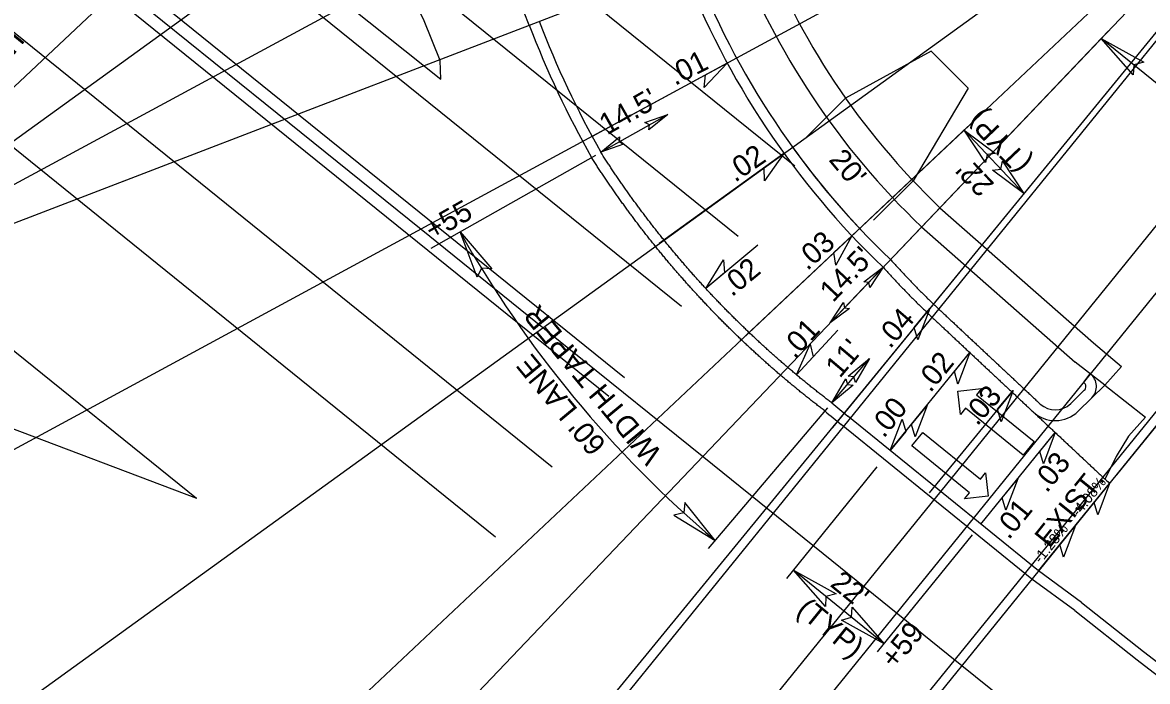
# Model space of a CAD drawing. Extents: x 1486489 to 1490134, y 497089 to 500876.
# Drawn here: x 1488844.3 to 1489056.4, y 499014.9 to 499139.1 of the extents above; entities that cross this region are included whole.
import ezdxf

# ---------------------------------------------------------------- set-up
doc = ezdxf.new("R2010")
doc.units = 0
for name, color, linetype in [('DEV PRELIMINARY STAMP CELL', 7, 'Continuous'), ('Gray Area Fill Shapes', 7, 'Continuous'), ('Old_Level_9', 7, 'Continuous'), ('Prop Conc Drive Radius Type', 7, 'Continuous'), ('Prop Conc Driveway', 7, 'Continuous'), ('Prop Horizontal Alignment Station Label', 7, 'Continuous'), ('Prop Rem of Exist Asph Pvmt', 7, 'Continuous'), ('Prop Text', 7, 'Continuous'), ('Scratch_Level_0', 7, 'Continuous'), ('Scratch_Level_5', 7, 'Continuous'), ('Sheet Border Standard 30in CELL', 7, 'Continuous'), ('Sheet Clip Boundary CELL', 7, 'Continuous'), ('Sheet Cutting Line CELL', 7, 'Continuous'), ('Sheet Data Field CELL', 7, 'Continuous'), ('Sheet Plan CELL', 7, 'Continuous'), ('Sheet Plot Border Inside CELL', 7, 'Continuous'), ('Sheet Plot Border Outside CELL', 7, 'Continuous'), ('Sheet Sticker Exception Certification CELL', 7, 'Continuous'), ('Sheet Title CELL', 7, 'Continuous')]:
    doc.layers.add(name, color=color, linetype=linetype)

msp = doc.modelspace()

# ---------------------------------------------------------------- linework, layer by layer
at = {"layer": 'DEV PRELIMINARY STAMP CELL'}
for p, q in [((1488982.96, 499097.13), (1488973.14, 499089)), ((1488998.04, 499081.13), (1488990.22, 499072.74)), ((1489007.94, 499058.43), (1489022.93, 499076.91)), ((1489025.03, 499044.57), (1489039.04, 499061.85)), ((1488988.42, 499034.35), (1489005.44, 499055.35)), ((1489005.51, 499020.49), (1489023.42, 499042.58)), ((1489006.77, 499022.04), (1488989.68, 499035.9))]:
    msp.add_line(p, q, dxfattribs=at)
for points in [[(1488973.14, 499089), (1488976.48, 499094.37), (1488976.7, 499091.95)], [(1488990.22, 499072.74), (1488992.85, 499078.5), (1488993.38, 499076.13)], [(1489022.93, 499076.91), (1489020.7, 499070.99), (1489020.02, 499073.32)], [(1489014.87, 499066.97), (1489012.64, 499061.05), (1489011.96, 499063.38)], [(1489007.94, 499058.43), (1489010.17, 499064.35), (1489010.85, 499062.02)], [(1489039.04, 499061.85), (1489036.81, 499055.93), (1489036.12, 499058.25)], [(1489031.96, 499053.12), (1489029.73, 499047.19), (1489029.04, 499049.52)], [(1489049.29, 499052.26), (1489047.06, 499046.34), (1489046.37, 499048.67)], [(1489042.83, 499044.3), (1489040.61, 499038.38), (1489039.92, 499040.71)], [(1488995.69, 499029.03), (1488989.68, 499035.9), (1488997.71, 499031.44), (1488995.81, 499030.92)], [(1489000.75, 499028.92), (1489006.77, 499022.04), (1488998.73, 499026.5), (1489000.63, 499027.02)]]:
    msp.add_lwpolyline(points, close=True, dxfattribs=at)
at = {"layer": 'Old_Level_9'}
msp.add_lwpolyline([(1489125.56, 498933.79), (1489105.79, 498950), (1489083.46, 498967.96), (1489053.28, 498992.22), (1489018.86, 499019.95), (1488995.28, 499038.96), (1488972.75, 499057.15), (1488947.35, 499077.62), (1488919.48, 499100.08), (1488890.07, 499123.82), (1488841.68, 499162.79)], dxfattribs=at)
at = {"layer": 'Prop Conc Drive Radius Type'}
msp.add_arc((1489113.94, 499205.5), 153.5, 215.8585, 223.5075, dxfattribs=at)
at = {"layer": 'Prop Conc Driveway'}
for p, q in [((1489015.64, 499133.75), (1488999.51, 499124.84)), ((1489022.63, 499126.72), (1489015.64, 499133.75)), ((1489022.63, 499126.72), (1489012.24, 499109.29)), ((1488999.51, 499124.84), (1488991.97, 499117.34)), ((1489012.24, 499109.29), (1489004.79, 499101.89))]:
    msp.add_line(p, q, dxfattribs=at)
at = {"layer": 'Prop Horizontal Alignment Station Label'}
for p, q in [((1489017.3, 499104.21), (1489046.26, 499078.72)), ((1489013.84, 499100.59), (1489042.81, 499075.1)), ((1489046.26, 499078.72), (1489051.56, 499074.32)), ((1489048.37, 499070.79), (1489042.81, 499075.1)), ((1489048.37, 499070.79), (1489051.56, 499074.32))]:
    msp.add_line(p, q, dxfattribs=at)
for radius in [140, 145]:
    msp.add_arc((1489113.94, 499205.5), radius, 201.0099, 226.343, dxfattribs=at)
at = {"layer": 'Prop Rem of Exist Asph Pvmt'}
for points in [[(1488923.18, 499128.44), (1488923.08, 499131.98), (1488920.07, 499139.43), (1488916.58, 499146.6), (1488912.5, 499153.45), (1488908.04, 499160.04), (1488903.34, 499166.45), (1488901.34, 499168.89)], [(1488852.51, 499162.38), (1488857.14, 499162.31), (1488868.78, 499160.49), (1488887.58, 499153.02), (1488906.23, 499141.98), (1488923.18, 499128.44)]]:
    msp.add_lwpolyline(points, dxfattribs=at)
at = {"layer": 'Prop Text'}
for p, q in [((1488774.7, 499063.04), (1489066.03, 499337.13)), ((1488858.52, 498937.81), (1489134.65, 499227.2)), ((1489133.24, 499228.47), (1488881.33, 498917.76)), ((1489156.48, 499209.63), (1488904.57, 498898.92)), ((1489167.42, 499200.76), (1488915.51, 498890.05)), ((1488916.88, 498888.94), (1489168.79, 499199.65))]:
    msp.add_line(p, q, dxfattribs=at)
msp.add_lwpolyline([(1488898.42, 498903.91), (1488898.42, 498903.91), (1489150.33, 499214.62)], dxfattribs=at)
at = {"layer": 'Scratch_Level_0'}
for p in [(1488772.04, 499134.22), (1488750.83, 499097.17)]:
    msp.add_line(p, (1488877.12, 499049.47), dxfattribs=at)
at = {"layer": 'Scratch_Level_5'}
for p, q in [((1489044.43, 499071.32), (1489045.65, 499072.9)), ((1489044.52, 499069.81), (1489041.95, 499067.29)), ((1489034.65, 499034.2), (1488998.7, 499063.35)), ((1489042.71, 499028.27), (1489034.65, 499034.2))]:
    msp.add_line(p, q, dxfattribs=at)
msp.add_lwpolyline([(1489042.71, 499028.27), (1489054.46, 499018.99), (1489094.18, 498988.49), (1489125.68, 498966.85), (1489130.23, 498964.14)], dxfattribs=at)
for centre, radius, start, end in [((1488796.55, 499083.6), 153.5, 21.0099, 51.1156), ((1489113.94, 499205.5), 153.5, 201.0099, 226.343), ((1489113.94, 499205.5), 186.5, 201.0099, 209.4913), ((1489043.82, 499070.53), 1, 314.53, 52.2567), ((1489039.05, 499070.24), 4.14, 226.9121, 314.53), ((1489113.94, 499205.5), 183, 229.7133, 230.9669)]:
    msp.add_arc(centre, radius, start, end, dxfattribs=at)
for points in [[(1488995.61, 499065.9), (1488994.92, 499066.43), (1488994.23, 499066.97), (1488993.53, 499067.5), (1488992.85, 499068.04), (1488992.16, 499068.59), (1488991.48, 499069.13), (1488990.8, 499069.68), (1488990.12, 499070.24), (1488989.44, 499070.8), (1488988.77, 499071.36), (1488988.1, 499071.92), (1488987.43, 499072.49), (1488986.76, 499073.06), (1488986.1, 499073.63), (1488985.44, 499074.21), (1488984.78, 499074.79), (1488984.13, 499075.37), (1488983.48, 499075.96), (1488982.83, 499076.55), (1488982.18, 499077.15), (1488981.53, 499077.74), (1488980.89, 499078.34), (1488980.25, 499078.95), (1488979.62, 499079.55), (1488978.98, 499080.16), (1488978.35, 499080.78), (1488977.72, 499081.39), (1488977.1, 499082.01), (1488976.47, 499082.64), (1488975.85, 499083.26), (1488975.24, 499083.89), (1488974.62, 499084.52), (1488974.01, 499085.16), (1488973.4, 499085.79), (1488972.8, 499086.44), (1488972.2, 499087.08), (1488971.6, 499087.73), (1488971, 499088.38), (1488970.41, 499089.03), (1488969.81, 499089.69), (1488969.23, 499090.35), (1488968.64, 499091.01), (1488968.06, 499091.67), (1488967.48, 499092.34), (1488966.91, 499093.01), (1488966.33, 499093.69), (1488965.76, 499094.36), (1488965.2, 499095.04), (1488964.63, 499095.73), (1488964.07, 499096.41), (1488963.52, 499097.1), (1488962.96, 499097.79), (1488962.41, 499098.49), (1488961.87, 499099.18), (1488961.32, 499099.88), (1488960.78, 499100.58), (1488960.24, 499101.29), (1488959.71, 499102), (1488959.18, 499102.71), (1488958.65, 499103.42), (1488958.12, 499104.14), (1488957.6, 499104.86), (1488957.08, 499105.58), (1488956.57, 499106.3), (1488956.06, 499107.03), (1488955.55, 499107.76), (1488955.05, 499108.49), (1488954.54, 499109.22), (1488954.05, 499109.96), (1488953.55, 499110.7), (1488953.06, 499111.44), (1488952.57, 499112.19), (1488951.61, 499113.69)], [(1489007.98, 499094.44), (1489008.47, 499093.9), (1489008.96, 499093.35), (1489009.46, 499092.81), (1489009.96, 499092.27), (1489010.46, 499091.73), (1489010.97, 499091.2), (1489011.47, 499090.67), (1489011.99, 499090.14), (1489012.5, 499089.61), (1489013.01, 499089.08), (1489013.53, 499088.56), (1489014.06, 499088.04), (1489014.58, 499087.52), (1489015.11, 499087), (1489015.64, 499086.49), (1489016.17, 499085.98), (1489016.71, 499085.46), (1489017.3, 499084.91), (1489017.9, 499084.35), (1489018.49, 499083.8), (1489019.08, 499083.24), (1489019.68, 499082.69), (1489020.27, 499082.13), (1489020.86, 499081.57), (1489021.46, 499081.02), (1489022.05, 499080.46), (1489022.64, 499079.91), (1489023.24, 499079.35), (1489023.83, 499078.8), (1489024.43, 499078.24), (1489025.02, 499077.69), (1489025.61, 499077.13), (1489026.21, 499076.58), (1489026.8, 499076.02), (1489027.39, 499075.47), (1489027.99, 499074.91), (1489028.58, 499074.36), (1489029.17, 499073.8), (1489029.77, 499073.25), (1489030.36, 499072.69), (1489030.96, 499072.14), (1489031.55, 499071.58), (1489032.14, 499071.02), (1489032.74, 499070.47), (1489033.33, 499069.91), (1489033.92, 499069.36), (1489034.52, 499068.8), (1489035.11, 499068.25), (1489035.7, 499067.69), (1489036.22, 499067.21)]]:
    msp.add_spline(points, degree=3, dxfattribs=at)
at = {"layer": 'Sheet Border Standard 30in CELL'}
for p, q in [((1489066.03, 499337.13), (1488774.7, 499063.04)), ((1488772.23, 499066.03), (1489096.5, 499300.23)), ((1489121.95, 499259.71), (1488770.16, 499069.32)), ((1488879.44, 498919.3), (1489132.96, 499228.7)), ((1489135.79, 499226.06), (1488844.47, 498951.95)), ((1488814, 498988.85), (1489138.26, 499223.06)), ((1489140.33, 499219.78), (1488788.55, 499029.37)), ((1488768.54, 499072.84), (1489141.95, 499216.25))]:
    msp.add_line(p, q, dxfattribs=at)
at = {"layer": 'Sheet Clip Boundary CELL'}
msp.add_arc((1489043.82, 499070.53), 3, 314.53, 52.2567, dxfattribs=at)
at = {"layer": 'Sheet Cutting Line CELL'}
for p, q in [((1489049.1, 499137.54), (1489008.6, 499095.1)), ((1489089.68, 499102.08), (1489047.72, 499136.1)), ((1488953.35, 499114.67), (1488965.97, 499121.81)), ((1488921.37, 499096.59), (1488952.41, 499114.14)), ((1489090.94, 499103.63), (1489050.58, 499053.85)), ((1488996.59, 499082.5), (1489006.6, 499093)), ((1488996.91, 499067.43), (1489004.02, 499075.82)), ((1488973.63, 499039.97), (1488996.14, 499066.52))]:
    msp.add_line(p, q, dxfattribs=at)
msp.add_arc((1489113.94, 499205.5), 215, 209.4913, 229.7133, dxfattribs=at)
at = {"layer": 'Sheet Data Field CELL'}
for p, q in [((1488977.19, 499131.48), (1488951.69, 499117.67)), ((1489022.54, 499119.5), (1489000.69, 499098.94)), ((1489033.14, 499106.87), (1489021.86, 499118.86)), ((1488987.89, 499114.45), (1488964.38, 499097.47)), ((1489034.4, 499108.42), (1489015.39, 499085.22)), ((1489000.69, 499098.94), (1488979.57, 499079.07)), ((1489015.39, 499085.22), (1488997.01, 499062.78)), ((1489031.11, 499069.79), (1489015.27, 499050.46))]:
    msp.add_line(p, q, dxfattribs=at)
for points in [[(1488977.19, 499131.48), (1488972.87, 499126.86), (1488973.12, 499129.27)], [(1489025.89, 499112.76), (1489021.86, 499118.86), (1489027.75, 499114.46), (1489026.19, 499114.25)], [(1488987.89, 499114.45), (1488984.2, 499109.31), (1488984.14, 499111.74)], [(1489029.11, 499112.97), (1489033.14, 499106.87), (1489027.24, 499111.27), (1489028.81, 499111.48)], [(1489000.69, 499098.94), (1488997.69, 499093.37), (1488997.32, 499095.77)], [(1489015.39, 499085.22), (1489013.13, 499079.31), (1489012.46, 499081.64)], [(1489031.11, 499069.79), (1489028.85, 499063.89), (1489028.17, 499066.22)]]:
    msp.add_lwpolyline(points, close=True, dxfattribs=at)
at = {"layer": 'Sheet Plan CELL'}
for p, q in [((1488989.91, 499112.07), (1488678.54, 499363.17)), ((1488667.87, 499349.94), (1488979.24, 499098.84)), ((1488968.56, 499085.6), (1488657.2, 499336.7)), ((1488646.42, 499323.34), (1488957.79, 499072.24)), ((1488954.87, 499068.62), (1488643.5, 499319.72)), ((1488632.83, 499306.48), (1488944.2, 499055.38)), ((1488933.52, 499042.15), (1488622.16, 499293.25))]:
    msp.add_line(p, q, dxfattribs=at)
at = {"layer": 'Sheet Plot Border Inside CELL'}
for p, q in [((1489020.7, 499069.64), (1489025.16, 499070.15)), ((1489021.19, 499065.25), (1489020.7, 499069.64)), ((1489025.16, 499070.15), (1489024.22, 499068.98)), ((1489024.22, 499068.98), (1489035.09, 499060.16)), ((1489022.14, 499066.42), (1489021.19, 499065.25)), ((1489033.01, 499057.6), (1489022.14, 499066.42)), ((1489012.01, 499059.31), (1489014.09, 499061.87)), ((1489014.09, 499061.87), (1489024.97, 499053.06)), ((1489035.09, 499060.16), (1489033.01, 499057.6)), ((1489022.89, 499050.49), (1489012.01, 499059.31)), ((1489024.97, 499053.06), (1489025.91, 499054.22)), ((1489025.91, 499054.22), (1489026.41, 499049.83)), ((1489021.94, 499049.33), (1489022.89, 499050.49)), ((1489026.41, 499049.83), (1489021.94, 499049.33))]:
    msp.add_line(p, q, dxfattribs=at)
at = {"layer": 'Sheet Plot Border Outside CELL'}
for points in [[(1489053.74, 499129.23), (1489047.72, 499136.1), (1489055.76, 499131.64), (1489053.86, 499131.12)], [(1488961.67, 499120.27), (1488965.97, 499121.81), (1488962.43, 499118.88), (1488962.53, 499119.86)], [(1488957.65, 499116.21), (1488953.35, 499114.67), (1488956.89, 499117.59), (1488956.79, 499116.61)], [(1488930.04, 499091.12), (1488926.8, 499099.65), (1488932.78, 499092.68), (1488930.82, 499092.85)], [(1489002.93, 499090.27), (1489006.6, 499093), (1489004.05, 499089.17), (1489003.87, 499090.14)], [(1489000.25, 499085.23), (1488996.59, 499082.5), (1488999.13, 499086.33), (1488999.31, 499085.36)], [(1488999.99, 499072.45), (1489004.02, 499075.82), (1489001.36, 499071.25), (1489001.08, 499072.35)], [(1489000.93, 499070.8), (1488996.91, 499067.43), (1488999.57, 499071.99), (1488999.84, 499070.89)], [(1488967.14, 499046.27), (1488974.92, 499041.49), (1488969.19, 499048.67), (1488968.99, 499046.71)]]:
    msp.add_lwpolyline(points, close=True, dxfattribs=at)
at = {"layer": 'Sheet Sticker Exception Certification CELL'}
for p, q in [((1489048.37, 499070.79), (1489043.36, 499065.86)), ((1489048.37, 499070.79), (1489056.05, 499064.71)), ((1489035.9, 499035.75), (1488999.95, 499064.9)), ((1489056.05, 499064.71), (1489052.88, 499061.14)), ((1489052.88, 499061.14), (1489050.53, 499057.32)), ((1489050.53, 499057.32), (1489048.37, 499053.01)), ((1489035.9, 499035.75), (1489049.29, 499052.26)), ((1489043.97, 499029.82), (1489035.9, 499035.75))]:
    msp.add_line(p, q, dxfattribs=at)
msp.add_lwpolyline([(1489043.97, 499029.82), (1489055.69, 499020.57), (1489095.36, 498990.11), (1489126.76, 498968.54), (1489131.27, 498965.85)], dxfattribs=at)
for centre, radius, start, end in [((1489113.94, 499205.5), 155.5, 201.0099, 226.343), ((1489113.94, 499205.5), 184.5, 201.0099, 209.4913), ((1489113.94, 499205.5), 181, 229.7133, 230.9669), ((1489039.05, 499070.24), 6.14, 226.9121, 314.53)]:
    msp.add_arc(centre, radius, start, end, dxfattribs=at)
for points in [[(1488996.91, 499067.43), (1488996.22, 499067.95), (1488995.53, 499068.48), (1488994.85, 499069.01), (1488994.17, 499069.54), (1488993.49, 499070.08), (1488992.81, 499070.62), (1488992.14, 499071.17), (1488991.47, 499071.71), (1488990.8, 499072.26), (1488990.13, 499072.82), (1488989.47, 499073.38), (1488988.81, 499073.94), (1488988.15, 499074.5), (1488987.49, 499075.07), (1488986.84, 499075.64), (1488986.19, 499076.21), (1488985.54, 499076.79), (1488984.89, 499077.37), (1488984.25, 499077.96), (1488983.61, 499078.54), (1488982.97, 499079.13), (1488982.34, 499079.73), (1488981.7, 499080.32), (1488981.07, 499080.92), (1488980.45, 499081.52), (1488979.82, 499082.13), (1488979.2, 499082.74), (1488978.58, 499083.35), (1488977.97, 499083.97), (1488977.35, 499084.59), (1488976.74, 499085.21), (1488976.13, 499085.83), (1488975.53, 499086.46), (1488974.93, 499087.09), (1488974.33, 499087.73), (1488973.73, 499088.36), (1488973.14, 499089), (1488972.55, 499089.65), (1488971.96, 499090.29), (1488971.37, 499090.94), (1488970.79, 499091.59), (1488970.21, 499092.25), (1488969.64, 499092.9), (1488969.06, 499093.57), (1488968.49, 499094.23), (1488967.93, 499094.9), (1488967.36, 499095.56), (1488966.8, 499096.24), (1488966.25, 499096.91), (1488965.69, 499097.59), (1488965.14, 499098.27), (1488964.59, 499098.95), (1488964.05, 499099.64), (1488963.51, 499100.33), (1488962.97, 499101.02), (1488962.43, 499101.72), (1488961.9, 499102.41), (1488961.37, 499103.11), (1488960.84, 499103.82), (1488960.32, 499104.52), (1488959.8, 499105.23), (1488959.28, 499105.94), (1488958.77, 499106.65), (1488958.26, 499107.37), (1488957.76, 499108.09), (1488957.25, 499108.81), (1488956.75, 499109.53), (1488956.26, 499110.26), (1488955.76, 499110.99), (1488955.27, 499111.72), (1488954.79, 499112.45), (1488954.3, 499113.19), (1488953.35, 499114.67)], [(1489006.6, 499093), (1489007.09, 499092.44), (1489007.59, 499091.89), (1489008.1, 499091.34), (1489008.61, 499090.8), (1489009.12, 499090.26), (1489009.63, 499089.71), (1489010.14, 499089.17), (1489010.66, 499088.64), (1489011.18, 499088.1), (1489011.7, 499087.57), (1489012.23, 499087.04), (1489012.76, 499086.51), (1489013.29, 499085.99), (1489013.83, 499085.47), (1489014.36, 499084.95), (1489014.9, 499084.43), (1489015.45, 499083.91), (1489016.04, 499083.35), (1489016.64, 499082.8), (1489017.23, 499082.24), (1489017.82, 499081.69), (1489018.42, 499081.13), (1489019.01, 499080.58), (1489019.6, 499080.02), (1489020.2, 499079.47), (1489020.79, 499078.91), (1489021.38, 499078.36), (1489021.98, 499077.8), (1489022.57, 499077.24), (1489023.17, 499076.69), (1489023.76, 499076.13), (1489024.35, 499075.58), (1489024.95, 499075.02), (1489025.54, 499074.47), (1489026.13, 499073.91), (1489026.73, 499073.36), (1489027.32, 499072.8), (1489027.91, 499072.25), (1489028.51, 499071.69), (1489029.1, 499071.14), (1489029.7, 499070.58), (1489030.29, 499070.03), (1489030.88, 499069.47), (1489031.48, 499068.92), (1489032.07, 499068.36), (1489032.66, 499067.81), (1489033.26, 499067.25), (1489033.85, 499066.69), (1489034.44, 499066.14), (1489035.04, 499065.58), (1489035.63, 499065.03), (1489036.23, 499064.47), (1489036.82, 499063.92), (1489037.41, 499063.36), (1489038.01, 499062.81), (1489038.6, 499062.25), (1489039.19, 499061.7), (1489039.79, 499061.14), (1489040.38, 499060.59), (1489040.97, 499060.03), (1489041.57, 499059.48), (1489042.16, 499058.92), (1489042.76, 499058.37), (1489043.35, 499057.81), (1489043.94, 499057.26), (1489044.54, 499056.7), (1489045.13, 499056.14), (1489045.72, 499055.59), (1489046.32, 499055.03), (1489046.91, 499054.48), (1489047.5, 499053.92), (1489048.1, 499053.37), (1489049.29, 499052.26)]]:
    msp.add_spline(points, degree=3, dxfattribs=at)

# ---------------------------------------------------------------- texts
at = {"layer": 'DEV PRELIMINARY STAMP CELL'}
for s, p in [("22'", (1488996.41, 499033.01)), ('(TYP)', (1488990.02, 499027.9))]:
    msp.add_text(s, height=4, rotation=320.9669, dxfattribs=at).set_placement(p)
at = {"layer": 'Gray Area Fill Shapes'}
for s, rotation, p in [('.02', 39.6023, (1488978.07, 499087.3)), ('.01', 47.017, (1488989.88, 499075.58)), ('.02', 50.9669, (1489015.5, 499069.21)), ('.00', 50.9669, (1489006.71, 499060.63)), ('.03', 50.9669, (1489037.44, 499050.31)), ('EXIST.', 51.0958, (1489037.95, 499039.88)), ('.01', 50.9669, (1489030.29, 499041.49)), ('+59', 50.9669, (1489008.81, 499017.06))]:
    msp.add_text(s, height=4, rotation=rotation, dxfattribs=at).set_placement(p)
at = {"layer": 'Old_Level_9'}
for s, p in [('-4.08%', (1489043.47, 499045.84)), ('-1.28%', (1489036.33, 499037.03))]:
    msp.add_text(s, height=2, rotation=51.4087, dxfattribs=at).set_placement(p)
at = {"layer": 'Sheet Cutting Line CELL'}
for s, rotation, p in [("14.5'", 29.4913, (1488954.52, 499117.83)), ("20'", 309.9201, (1488996.19, 499113.19)), ('+55', 29.4913, (1488921.61, 499097.96)), ("14.5'", 46.343, (1488997.14, 499086.23)), ('WIDTH TAPER', 129.6023, (1488965.09, 499057.9)), ("60' LANE", 129.6023, (1488954.55, 499059.66))]:
    msp.add_text(s, height=4, rotation=rotation, dxfattribs=at).set_placement(p)
at = {"layer": 'Sheet Data Field CELL'}
for s, rotation, p in [('.01', 27.0484, (1488967.34, 499127.16)), ('(TYP)', 133.4493, (1489034.74, 499112.92)), ('.02', 34.4631, (1488978.67, 499108.89)), ("22'", 133.4493, (1489027.73, 499108.68)), ('.03', 41.8779, (1488992.27, 499092.24)), ('.04', 49.2926, (1489007.9, 499077.49)), ('.03', 49.2926, (1489024.33, 499062.93))]:
    msp.add_text(s, height=4, rotation=rotation, dxfattribs=at).set_placement(p)
at = {"layer": 'Sheet Title CELL'}
for s, rotation, p in [('RR EQUIPTMENT', 51.1156, (1488817.72, 499102.02)), ("11'", 49.7133, (1488998.42, 499071.95))]:
    msp.add_text(s, height=4, rotation=rotation, dxfattribs=at).set_placement(p)

doc.saveas('drawing.dxf')
